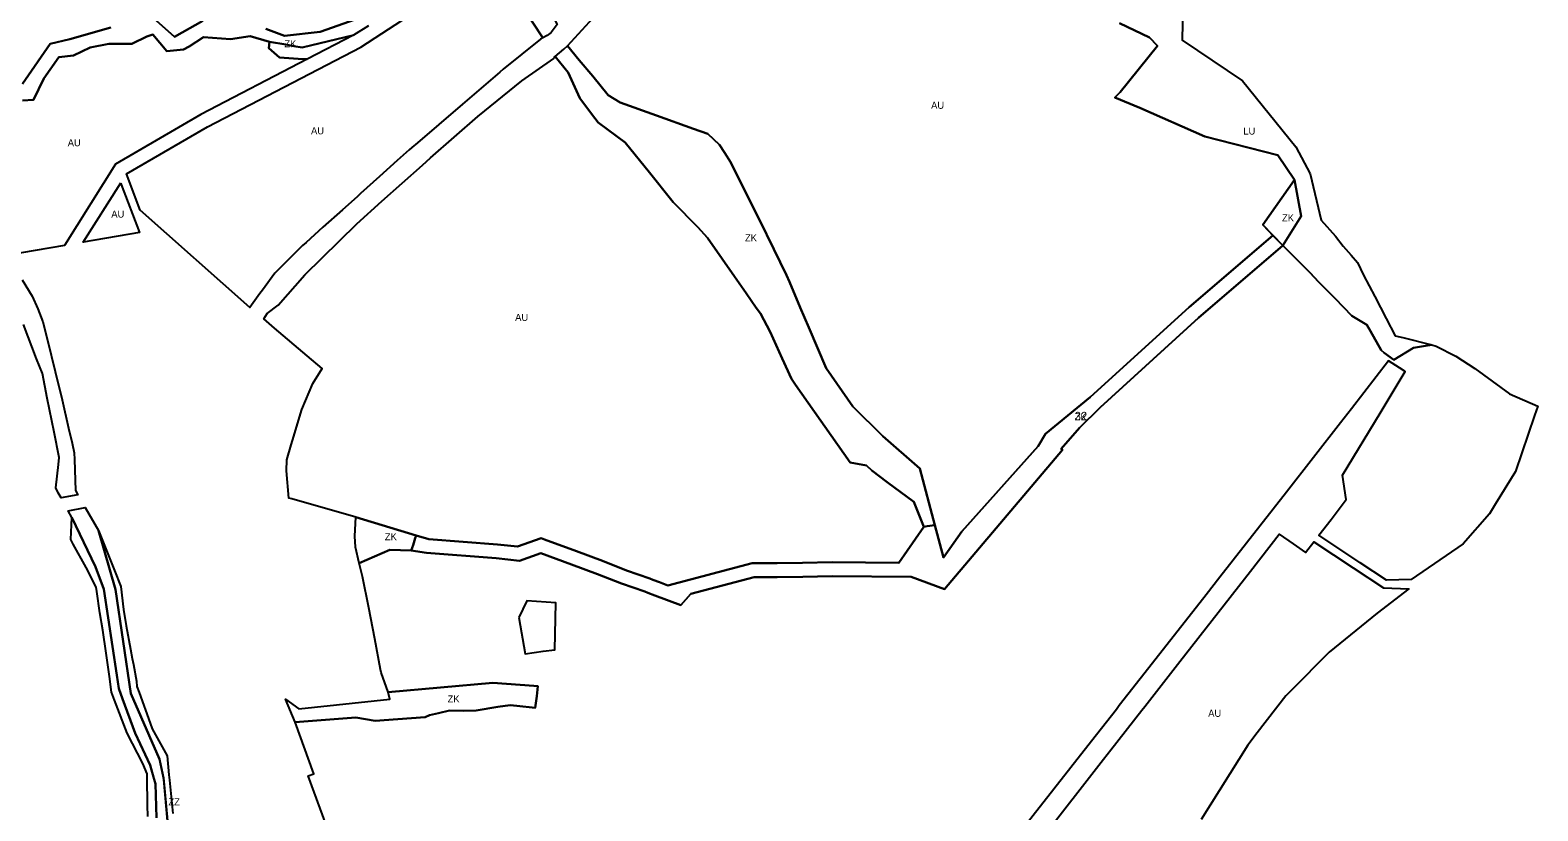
# Model space of a CAD drawing. Extents: x -521261 to -517465, y -1182764 to -1179456.
# Drawn here: x -519568 to -518493, y -1180835 to -1180279 of the extents above; entities that cross this region are included whole.
import ezdxf

# ---------------------------------------------------------------- set-up
doc = ezdxf.new("R2010")
doc.units = 0
for name, color, linetype in [('90640013', 7, 'Continuous'), ('90670013', 7, 'Continuous'), ('90710013', 7, 'Continuous'), ('90710023', 7, 'Continuous'), ('90750013', 7, 'Continuous'), ('90770013', 7, 'Continuous'), ('ID_navrh', 7, 'Continuous')]:
    doc.layers.add(name, color=color, linetype=linetype)

msp = doc.modelspace()

# ---------------------------------------------------------------- linework, layer by layer
at = {"layer": '90640013'}
for points in [[(-519478.49, -1180271.77), (-519465.42, -1180283.42), (-519445.16, -1180272.07)], [(-519400.33, -1180277.79), (-519386.97, -1180282.76), (-519361.62, -1180279.74), (-519336.67, -1180271.06)], [(-519327.14, -1180275.48), (-519337.72, -1180282.23), (-519374.35, -1180291.1), (-519380.4, -1180290.14), (-519385.91, -1180288.91), (-519397.66, -1180286.85), (-519411.38, -1180282.85), (-519425.51, -1180285.07), (-519444.64, -1180283.6), (-519455.05, -1180290.29), (-519459, -1180292.35), (-519470.8, -1180293.54), (-519480.94, -1180281.79), (-519485.19, -1180283.09), (-519495.78, -1180288.48), (-519512.22, -1180288.37), (-519525.53, -1180291.06), (-519537.37, -1180296.63), (-519547.78, -1180297.83), (-519558.51, -1180313.01), (-519565.96, -1180328.26), (-519573.82, -1180328.67)], [(-519573.76, -1180316.82), (-519554.18, -1180288.28), (-519540.12, -1180284.95), (-519510.88, -1180276.77)], [(-519574.08, -1180456.6), (-519566.87, -1180468.21), (-519562.94, -1180477.16), (-519559.25, -1180486.48), (-519556.06, -1180499.53), (-519550.45, -1180521.83), (-519545.59, -1180542.18), (-519541.11, -1180562.36), (-519538.35, -1180572.99), (-519537.04, -1180579.93), (-519536.72, -1180584.57), (-519536.05, -1180606.88), (-519534.35, -1180609.75), (-519546.312, -1180612.038), (-519546.312, -1180612.038), (-519548.25, -1180608.47), (-519550.02, -1180604.84), (-519548.23, -1180588.14), (-519547.64, -1180583.16), (-519551.14, -1180565.07), (-519556.23, -1180540.88), (-519559.42, -1180523.34), (-519563.84, -1180512.91), (-519573.18, -1180488.44)], [(-519478.12, -1180840), (-519478.91, -1180815.91), (-519482.79, -1180802.48), (-519493.4, -1180779.68), (-519502.51, -1180755.33), (-519505.21, -1180747.78), (-519506.63, -1180738.29), (-519515.84, -1180677.04), (-519521.8, -1180661.26), (-519538.72, -1180626.02), (-519541.304, -1180621.261), (-519529.021, -1180618.912), (-519519.49, -1180635.3), (-519507.5, -1180677.34), (-519496.47, -1180751.4), (-519475.99, -1180798.26), (-519473.15, -1180811.61), (-519470.44, -1180842.25)]]:
    msp.add_lwpolyline(points, dxfattribs=at)
at = {"layer": '90670013'}
for points in [[(-519484.35, -1180839.02), (-519484.62, -1180831.05), (-519484.955, -1180811.364), (-519485, -1180808.75), (-519488.01, -1180801.32), (-519499.04, -1180779.81), (-519508.12, -1180756.22), (-519510.24, -1180750.45), (-519511.64, -1180739.35), (-519514.02, -1180722.61), (-519516.57, -1180706.21), (-519518.61, -1180693.85), (-519520.86, -1180678.68), (-519521.28, -1180675.74), (-519528.51, -1180661.68), (-519537.56, -1180645.04), (-519539.34, -1180641.78), (-519538.72, -1180626.02), (-519521.8, -1180661.26), (-519515.84, -1180677.04), (-519506.63, -1180738.29), (-519505.21, -1180747.78), (-519502.51, -1180755.33), (-519493.4, -1180779.68), (-519482.79, -1180802.48), (-519480.052, -1180811.957), (-519478.91, -1180815.91), (-519478.12, -1180840)], [(-519470.44, -1180842.25), (-519473.044, -1180812.806), (-519473.15, -1180811.61), (-519475.99, -1180798.26), (-519496.47, -1180751.4), (-519507.5, -1180677.34), (-519519.49, -1180635.3), (-519508.15, -1180663.81), (-519503.59, -1180675.27), (-519501.68, -1180691.54), (-519499.82, -1180703.19), (-519496.79, -1180719.89), (-519495.56, -1180726.51), (-519494.71, -1180730.9), (-519492.42, -1180742.78), (-519492.22, -1180746.44), (-519490.66, -1180750.76), (-519482.84, -1180772.64), (-519481.25, -1180776.67), (-519470.74, -1180795.81), (-519469.45, -1180809.39), (-519469.058, -1180813.289), (-519466.67, -1180837.06)]]:
    msp.add_lwpolyline(points, dxfattribs=at)
at = {"layer": '90710013'}
for points in [[(-519223.962, -1180251.695), (-519238.561, -1180229.516), (-519220.038, -1180217.438), (-519217.87, -1180223.87), (-519208.134, -1180243.38), (-519196.738, -1180266.217), (-519192.584, -1180274.543), (-519196.77, -1180280.19), (-519199.69, -1180282.36), (-519202.667, -1180284.047)], [(-519398.05, -1180291.51), (-519397.66, -1180286.85), (-519385.91, -1180288.91), (-519380.4, -1180290.14), (-519374.35, -1180291.1), (-519337.818, -1180282.254), (-519370.805, -1180299.397), (-519373.839, -1180299.209), (-519390.429, -1180298.181)], [(-519126.717, -1180380.2), (-519144.03, -1180358.73), (-519163.2, -1180344.4), (-519168.04, -1180338.25), (-519176.29, -1180327.1), (-519184.62, -1180308.69), (-519193.89, -1180297.38), (-519187.77, -1180292.28), (-519185.02, -1180289.7), (-519176.72, -1180300.12), (-519167.13, -1180311.47), (-519156.01, -1180324.9), (-519147.65, -1180330.09), (-519121.578, -1180339.469), (-519095.283, -1180348.928), (-519085.02, -1180352.62), (-519076.79, -1180360.27), (-519073.107, -1180365.926), (-519068.56, -1180372.91), (-519059.773, -1180390.689), (-519048.288, -1180413.924), (-519037.953, -1180434.835), (-519028.89, -1180453.17), (-519026.832, -1180458.019), (-519019.073, -1180476.293), (-519012.969, -1180490.672), (-519000.68, -1180519.62), (-518981.57, -1180546.96), (-518960.12, -1180568.13), (-518933.81, -1180591.04), (-518923.198, -1180631.358), (-518928.505, -1180632.167), (-518931.02, -1180632.55), (-518938.04, -1180614.84), (-518957.18, -1180600.74), (-518967.98, -1180592.51), (-518971.94, -1180589.02), (-518983.49, -1180586.91), (-519022.499, -1180531.341), (-519025.42, -1180527.18), (-519032.04, -1180512.65), (-519040.51, -1180493.58), (-519047.53, -1180480.71), (-519050.56, -1180476.44), (-519057.81, -1180466.19), (-519066.1, -1180454.21), (-519074.75, -1180441.61), (-519085.36, -1180426.67), (-519092.23, -1180419.01), (-519109.67, -1180401.34), (-519110.642, -1180400.134)], [(-518661.93, -1180411.14), (-518675.05, -1180432.18), (-518689.17, -1180417.51), (-518666.6, -1180385.39)], [(-519295.07, -1180645.74), (-519296.664, -1180649.586), (-519311.76, -1180648.99), (-519333.71, -1180658.56), (-519336.36, -1180647.15), (-519336.86, -1180639.29), (-519336.13, -1180625.82), (-519293.11, -1180638.89), (-519293.69, -1180640.85)], [(-519209.21, -1180745.99), (-519206.18, -1180746.33), (-519207.07, -1180753.38), (-519208.14, -1180761.67), (-519221.15, -1180760.28), (-519226.07, -1180759.84), (-519234.69, -1180761.03), (-519250.14, -1180763.5), (-519259.51, -1180763.83), (-519269.35, -1180763.63), (-519277.02, -1180765.53), (-519283.48, -1180766.89), (-519286.57, -1180768.38), (-519306.03, -1180769.68), (-519322.21, -1180771.06), (-519336.04, -1180768.64), (-519379.31, -1180771.85), (-519386.31, -1180755.46), (-519376.82, -1180762.28), (-519311.73, -1180755.57), (-519313.1, -1180750.61), (-519238.37, -1180743.8)]]:
    msp.add_lwpolyline(points, close=True, dxfattribs=at)
at = {"layer": '90710023'}
msp.add_lwpolyline([(-518741.689, -1180476.192), (-518681.996, -1180424.963), (-518675.05, -1180432.18), (-518735.07, -1180483.69), (-518805.34, -1180547.49), (-518819.9, -1180562.16), (-518832.97, -1180577.12), (-518832.02, -1180577.88), (-518916.181, -1180676.98), (-518940.14, -1180668.41), (-518996.34, -1180667.9), (-519017.31, -1180668.38), (-519035.6, -1180668.57), (-519052.05, -1180668.61), (-519097.2, -1180680.42), (-519104.261, -1180688.473), (-519122.814, -1180681.623), (-519127.912, -1180679.815), (-519130.077, -1180678.867), (-519146.49, -1180673.063), (-519163.737, -1180666.312), (-519182.177, -1180659.446), (-519204.136, -1180651.335), (-519219.445, -1180656.878), (-519236.043, -1180655.109), (-519285.79, -1180651.286), (-519296.664, -1180649.586), (-519295.07, -1180645.74), (-519293.69, -1180640.85), (-519293.11, -1180638.89), (-519284.06, -1180641.39), (-519235.13, -1180645.15), (-519220.68, -1180646.69), (-519204, -1180640.65), (-519201.63, -1180641.6), (-519178.7, -1180650.07), (-519160.17, -1180656.97), (-519143, -1180663.69), (-519126.4, -1180669.56), (-519124.23, -1180670.51), (-519119.41, -1180672.22), (-519113.587, -1180674.37), (-519053.348, -1180658.613), (-519035.664, -1180658.57), (-519017.476, -1180658.381), (-518996.409, -1180657.899), (-518948.854, -1180658.331), (-518931.02, -1180632.55), (-518928.505, -1180632.167), (-518923.198, -1180631.358), (-518917.08, -1180654.6), (-518903.85, -1180636.05), (-518849.54, -1180575.21), (-518844.2, -1180566.48), (-518812.255, -1180540.261)], close=True, dxfattribs=at)
at = {"layer": '90750013'}
for points in [[(-519223.962, -1180251.695), (-519202.667, -1180284.047), (-519204.49, -1180285.08), (-519231.03, -1180306.54), (-519233.45, -1180308.61), (-519259.97, -1180331.39), (-519293.87, -1180360.31), (-519294.53, -1180360.9), (-519297.95, -1180363.96), (-519306.52, -1180371.63), (-519319.18, -1180382.98), (-519332.64, -1180395.04), (-519335.21, -1180397.34), (-519345.54, -1180406.59), (-519359.51, -1180419.1), (-519371.54, -1180429.87), (-519374.1, -1180432.17), (-519383.14, -1180441.22), (-519393.56, -1180451.65), (-519393.86, -1180451.93), (-519402.68, -1180463.97), (-519404.46, -1180466.41), (-519411.56, -1180476.2), (-519489.994, -1180406.887), (-519499.747, -1180381.157), (-519441.802, -1180347.563), (-519332.465, -1180290.741), (-519238.561, -1180229.516)], [(-518791.47, -1180273.65), (-518769.97, -1180283.94), (-518764.31, -1180289.83), (-518791.03, -1180322.79), (-518794.77, -1180326.6), (-518776.93, -1180333.89), (-518730.54, -1180354.36), (-518678.54, -1180367.65), (-518666.6, -1180385.39), (-518689.17, -1180417.51), (-518681.996, -1180424.963), (-518741.689, -1180476.192), (-518812.255, -1180540.261), (-518844.2, -1180566.48), (-518849.54, -1180575.21), (-518903.85, -1180636.05), (-518917.08, -1180654.6), (-518923.198, -1180631.358), (-518933.81, -1180591.04), (-518960.12, -1180568.13), (-518981.57, -1180546.96), (-519000.68, -1180519.62), (-519012.969, -1180490.672), (-519019.073, -1180476.293), (-519026.832, -1180458.019), (-519028.89, -1180453.17), (-519037.953, -1180434.835), (-519048.288, -1180413.924), (-519059.773, -1180390.689), (-519068.56, -1180372.91), (-519073.107, -1180365.926), (-519076.79, -1180360.27), (-519085.02, -1180352.62), (-519095.283, -1180348.928), (-519121.578, -1180339.469), (-519147.65, -1180330.09), (-519156.01, -1180324.9), (-519167.13, -1180311.47), (-519176.72, -1180300.12), (-519185.02, -1180289.7), (-519143.34, -1180243.85)], [(-519445.16, -1180272.07), (-519465.42, -1180283.42), (-519478.49, -1180271.77)], [(-519336.67, -1180271.06), (-519361.62, -1180279.74), (-519386.97, -1180282.76), (-519400.33, -1180277.79)], [(-519573.82, -1180328.67), (-519565.96, -1180328.26), (-519558.51, -1180313.01), (-519547.78, -1180297.83), (-519537.37, -1180296.63), (-519525.53, -1180291.06), (-519512.22, -1180288.37), (-519495.78, -1180288.48), (-519485.19, -1180283.09), (-519480.94, -1180281.79), (-519470.8, -1180293.54), (-519459, -1180292.35), (-519455.05, -1180290.29), (-519444.64, -1180283.6), (-519425.51, -1180285.07), (-519411.38, -1180282.85), (-519397.66, -1180286.85), (-519398.05, -1180291.51), (-519390.429, -1180298.181), (-519373.839, -1180299.209), (-519370.805, -1180299.397), (-519446.618, -1180338.797), (-519507.413, -1180374.043), (-519543.828, -1180432.113), (-519595.6, -1180440.97)], [(-519510.88, -1180276.77), (-519540.12, -1180284.95), (-519554.18, -1180288.28), (-519573.76, -1180316.82)], [(-519346.93, -1180872.84), (-519370.039, -1180810.159), (-519365.939, -1180808.674), (-519379.31, -1180771.85), (-519336.04, -1180768.64), (-519322.21, -1180771.06), (-519306.03, -1180769.68), (-519286.57, -1180768.38), (-519283.48, -1180766.89), (-519277.02, -1180765.53), (-519269.35, -1180763.63), (-519259.51, -1180763.83), (-519250.14, -1180763.5), (-519234.69, -1180761.03), (-519226.07, -1180759.84), (-519221.15, -1180760.28), (-519208.14, -1180761.67), (-519207.07, -1180753.38), (-519206.18, -1180746.33), (-519209.21, -1180745.99), (-519238.37, -1180743.8), (-519313.1, -1180750.61), (-519318.07, -1180736.59), (-519318.54, -1180734.26), (-519322.63, -1180712.39), (-519326.84, -1180690.31), (-519331.34, -1180668.18), (-519333.71, -1180658.56), (-519311.76, -1180648.99), (-519296.664, -1180649.586), (-519285.79, -1180651.286), (-519236.043, -1180655.109), (-519219.445, -1180656.878), (-519204.136, -1180651.335), (-519182.177, -1180659.446), (-519163.737, -1180666.312), (-519146.49, -1180673.063), (-519130.077, -1180678.867), (-519127.912, -1180679.815), (-519122.814, -1180681.623), (-519104.261, -1180688.473), (-519097.2, -1180680.42), (-519052.05, -1180668.61), (-519035.6, -1180668.57), (-519017.31, -1180668.38), (-518996.34, -1180667.9), (-518940.14, -1180668.41), (-518916.181, -1180676.98), (-518832.02, -1180577.88), (-518832.97, -1180577.12), (-518819.9, -1180562.16), (-518805.34, -1180547.49), (-518735.07, -1180483.69), (-518675.05, -1180432.18), (-518661.47, -1180445.76), (-518655.36, -1180451.69), (-518649.56, -1180457.93), (-518637.61, -1180469.87), (-518625.72, -1180482.18), (-518615, -1180488.64), (-518612.32, -1180493.17), (-518604.91, -1180506.68), (-518602.71, -1180508.55), (-518595.68, -1180513.69), (-518581.71, -1180505.17), (-518573.33, -1180503.74), (-518568.75, -1180502.95), (-518565.5, -1180503.79), (-518551.48, -1180511.06), (-518538.07, -1180519.79), (-518513.23, -1180537.84), (-518493.09, -1180546.62), (-518495.38, -1180553.32), (-518509.07, -1180593.32), (-518523.28, -1180616.38), (-518527.66, -1180623.46), (-518546.41, -1180644.74), (-518583.43, -1180670.18), (-518600.95, -1180670.78), (-518619.78, -1180658.29), (-518649.3, -1180638.71), (-518640.58, -1180627.39), (-518629.68, -1180613.23), (-518632.43, -1180595.93), (-518605.66, -1180551.61), (-518587.79, -1180521.97), (-518591.76, -1180519.42), (-518599.7, -1180514.3), (-518626.09, -1180548.61), (-518633.73, -1180558.55), (-518672.36, -1180607.93), (-518719.82, -1180668.45), (-518729.72, -1180681.1), (-518770.41, -1180733.05), (-518791.61, -1180760.13), (-518793.68, -1180762.77), (-518811.46, -1180785.47), (-518879.81, -1180872.74)], [(-518847.08, -1180854.98), (-518802.83, -1180798.37), (-518797.69, -1180791.72), (-518775.57, -1180763.41), (-518773.42, -1180760.66), (-518748.4, -1180728.62), (-518698.12, -1180664.22), (-518677.5, -1180637.82), (-518667.48, -1180644.84), (-518658.73, -1180650.97), (-518652.93, -1180643.43), (-518624.83, -1180661.96), (-518603.24, -1180676.18), (-518584.99, -1180676.84), (-518607.61, -1180694.31), (-518642.03, -1180722.06), (-518652.84, -1180732.99), (-518658.13, -1180738.33), (-518672.88, -1180753.24), (-518693.17, -1180779.5), (-518699.96, -1180788.29), (-518733.13, -1180841.32)]]:
    msp.add_lwpolyline(points, dxfattribs=at)
for points in [[(-518931.02, -1180632.55), (-518948.854, -1180658.331), (-518996.409, -1180657.899), (-519017.476, -1180658.381), (-519035.664, -1180658.57), (-519053.348, -1180658.613), (-519113.587, -1180674.37), (-519119.41, -1180672.22), (-519124.23, -1180670.51), (-519126.4, -1180669.56), (-519143, -1180663.69), (-519160.17, -1180656.97), (-519178.7, -1180650.07), (-519201.63, -1180641.6), (-519204, -1180640.65), (-519220.68, -1180646.69), (-519235.13, -1180645.15), (-519284.06, -1180641.39), (-519293.11, -1180638.89), (-519336.13, -1180625.82), (-519381.66, -1180612.73), (-519383.82, -1180612.18), (-519385.56, -1180592.85), (-519385.237, -1180584.881), (-519382.165, -1180574.166), (-519381.262, -1180571.015), (-519374.499, -1180548.968), (-519366.63, -1180530.605), (-519360.156, -1180519.907), (-519370.82, -1180510.84), (-519394.031, -1180491.104), (-519401.789, -1180484.508), (-519399.4, -1180480.67), (-519391.52, -1180474.74), (-519372.45, -1180453), (-519335.47, -1180416.78), (-519317.6, -1180400.45), (-519288.55, -1180374.8), (-519282.81, -1180369.73), (-519249.16, -1180340.26), (-519217.64, -1180314.85), (-519194.84, -1180298.72), (-519194.54, -1180297.83), (-519193.89, -1180297.38), (-519184.62, -1180308.69), (-519176.29, -1180327.1), (-519168.04, -1180338.25), (-519163.2, -1180344.4), (-519144.03, -1180358.73), (-519126.717, -1180380.2), (-519110.642, -1180400.134), (-519109.67, -1180401.34), (-519092.23, -1180419.01), (-519085.36, -1180426.67), (-519074.75, -1180441.61), (-519066.1, -1180454.21), (-519057.81, -1180466.19), (-519050.56, -1180476.44), (-519047.53, -1180480.71), (-519040.51, -1180493.58), (-519032.04, -1180512.65), (-519025.42, -1180527.18), (-519022.499, -1180531.341), (-518983.49, -1180586.91), (-518971.94, -1180589.02), (-518967.98, -1180592.51), (-518957.18, -1180600.74), (-518938.04, -1180614.84)], [(-519503.729, -1180387.445), (-519503.318, -1180388.536), (-519490.35, -1180422.965), (-519530.579, -1180429.847)], [(-519219.9, -1180697.33), (-519215.32, -1180723.28), (-519202.56, -1180721.35), (-519194.14, -1180720.3), (-519193.43, -1180686.91), (-519214.15, -1180685.3)]]:
    msp.add_lwpolyline(points, close=True, dxfattribs=at)
at = {"layer": '90770013'}
msp.add_lwpolyline([(-518746.13, -1180248.91), (-518746.71, -1180285.66), (-518703.81, -1180314.81), (-518665.78, -1180361.68), (-518655.44, -1180381.08), (-518647.53, -1180414.17), (-518637.32, -1180425.55), (-518631.95, -1180432.51), (-518626.32, -1180439.08), (-518621.78, -1180444.3), (-518617.44, -1180453.19), (-518609.3, -1180468.45), (-518601.16, -1180484.23), (-518594.75, -1180496.62), (-518589.35, -1180497.6), (-518568.75, -1180502.95), (-518573.33, -1180503.74), (-518581.71, -1180505.17), (-518595.68, -1180513.69), (-518602.71, -1180508.55), (-518604.91, -1180506.68), (-518612.32, -1180493.17), (-518615, -1180488.64), (-518625.72, -1180482.18), (-518637.61, -1180469.87), (-518649.56, -1180457.93), (-518655.36, -1180451.69), (-518661.47, -1180445.76), (-518675.05, -1180432.18), (-518661.93, -1180411.14), (-518666.6, -1180385.39), (-518678.54, -1180367.65), (-518730.54, -1180354.36), (-518776.93, -1180333.89), (-518794.77, -1180326.6), (-518791.03, -1180322.79), (-518764.31, -1180289.83), (-518769.97, -1180283.94), (-518791.47, -1180273.65)], dxfattribs=at)

# ---------------------------------------------------------------- texts
at = {"layer": '90670013'}
msp.add_text('ZZ', height=5, rotation=0, dxfattribs=at).set_placement((-519469.705, -1180831.172))
at = {"layer": '90710013'}
for rotation, p in [(360, (-519387.036, -1180290.825)), (360, (-518675.55, -1180414.894)), (360, (-519058.544, -1180429.152)), (360, (-519315.372, -1180642.19)), (0, (-519270.624, -1180757.825))]:
    msp.add_text('ZK', height=5, rotation=rotation, dxfattribs=at).set_placement(p)
at = {"layer": '90710023'}
msp.add_text('ZK', height=5, rotation=360, dxfattribs=at).set_placement((-518823.402, -1180556.718))
at = {"layer": '90750013'}
for rotation, p in [(0, (-518925.81, -1180334.699)), (360, (-519368.035, -1180352.858)), (360, (-519541.544, -1180361.38)), (0, (-519510.465, -1180412.244)), (360, (-519222.447, -1180485.875)), (360, (-518728.195, -1180768.086))]:
    msp.add_text('AU', height=5, rotation=rotation, dxfattribs=at).set_placement(p)
at = {"layer": '90770013'}
msp.add_text('LU', height=5, rotation=0, dxfattribs=at).set_placement((-518703.138, -1180353.055))
at = {"layer": 'ID_navrh'}
msp.add_text('32', height=6, rotation=0, dxfattribs=at).set_placement((-518823.402, -1180556.718))

doc.saveas('drawing.dxf')
